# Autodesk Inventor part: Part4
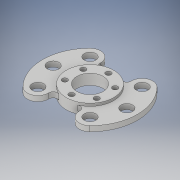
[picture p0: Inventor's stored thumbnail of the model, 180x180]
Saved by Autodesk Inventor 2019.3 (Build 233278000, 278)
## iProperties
Created: 2019-02
Part Number: Part4
Material: Generic
Document SubType Name: Modeling
Designer: Synergysoft
Density: 1 g/cm^3
Appearance: Default
Author: Synergysoft
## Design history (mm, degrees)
sketch "Sketch1" dims "d1" = 70, "d8" = 140
  geometry: C1 r 25 at (0, 0); C2 r 5 at (0, -35); C3 r 5 at (30.311, -17.5); C4 r 5 at (30.311, 17.5); C5 r 5 at (0, 35); C6 r 5 at (-30.311, 17.5); C7 r 5 at (-30.311, -17.5); C8 r 11 at (70, 0); C9 r 11 at (49.497, 49.497); C10 r 11 at (0, 70); C11 r 11 at (-49.497, 49.497); C12 r 11 at (-70, 0); C13 r 11 at (-49.497, -49.497); C14 r 11 at (0, -70); C15 r 11 at (49.497, -49.497); A1 r 45 centre (0, 0) between (18.27, -41.124) and (-18.27, -41.124); A2 r 20 centre (49.497, -49.497) between (29.512, -48.739) and (63.64, -63.64); A3 r 8 centre (21.518, -48.435) between (29.512, -48.739) and (18.27, -41.124); A4 r 20 centre (49.497, 49.497) between (29.512, 48.739) and (63.64, 63.64); A5 r 20 centre (-49.497, 49.497) between (-29.512, 48.739) and (-63.64, 63.64); A6 r 20 centre (-49.497, -49.497) between (-29.512, -48.739) and (-63.64, -63.64); A7 r 8 centre (-21.518, -48.435) between (-18.27, -41.124) and (-29.512, -48.739); A8 r 8 centre (21.518, 48.435) between (18.27, 41.124) and (29.512, 48.739); A9 r 8 centre (-21.518, 48.435) between (-29.512, 48.739) and (-18.27, 41.124); A10 r 90 centre (0, 0) between (63.64, -63.64) and (63.64, 63.64); A11 r 90 centre (0, 0) between (-63.64, 63.64) and (-63.64, -63.64); 3 further points
  constraints: 26 centre point, 24 point on circle, 9 coincident, 8 tangent, 2 horizontal alignment, 2 vertical alignment, 34 other
  dimensions: "d0" = 50 diameter of C1; "d2" = 90 diameter of A1; "d3" = 10 diameter of C2; "d6" = 360 deg dimension on point (0, 0) C2.centre (derived); "d10" = 22 diameter of C8; "d13" = 360 deg dimension on point (0, 0) C8.centre (derived); "d15" = 20 radius of A2; "d16" = 8 radius of A3; "d17" = 20 radius of A4; "d18" = 20 radius of A5; "d19" = 20 radius of A6; "d20" = 8 radius of A7; "d21" = 8 radius of A8; "d22" = 8 radius of A9; "d23" = 90 radius of A10; "d24" = 90 radius of A11
extrude "Extrusion1" new body sketch "Sketch1" stored distance "d25" = 10; taper "d26" = 0 deg
extrude "Extrusion2" join sketch "Sketch1" stored distance "d27" = 20; taper "d28" = 0 deg
body "Solid1"
